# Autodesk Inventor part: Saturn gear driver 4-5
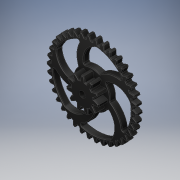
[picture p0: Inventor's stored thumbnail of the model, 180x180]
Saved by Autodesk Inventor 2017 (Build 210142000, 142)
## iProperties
Created: 2016-06
Part Number: Saturn gear driver 4-5
Material: Generic
Document SubType Name: Modeling
Designer: Stan
Density: 1 g/cm^3
Appearance: Glossy - Black
Author: Stan
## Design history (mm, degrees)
sketch "Sketch1"
  geometry: A1 r 17.842 centre (23.318, -32.57) between (7.78, -41.34) and (10.377, -44.853); A2 r 17.842 centre (23.318, -32.57) between (7.78, -41.34) and (10.377, -44.853); A3 r 17.842 centre (-11.479, -38.377) between (4.749, -45.792) and (6.065, -41.626); A4 r 17.842 centre (-11.479, -38.377) between (4.749, -45.792) and (6.065, -41.626); A5 r 17.842 centre (28.361, -28.288) between (14.478, -39.495) and (17.618, -42.533); A6 r 17.842 centre (28.361, -28.288) between (14.478, -39.495) and (17.618, -42.533); A7 r 17.842 centre (-5.006, -39.743) between (12.222, -44.386) and (12.833, -40.06); A8 r 17.842 centre (-5.006, -39.743) between (12.222, -44.386) and (12.833, -40.06); A9 r 17.842 centre (32.631, -23.234) between (20.781, -36.574) and (24.378, -39.053); A10 r 17.842 centre (32.631, -23.234) between (20.781, -36.574) and (24.378, -39.053); A11 r 17.842 centre (1.603, -40.025) between (19.361, -41.769) and (19.252, -37.401); A12 r 17.842 centre (1.603, -40.025) between (19.361, -41.769) and (19.252, -37.401); A13 r 17.842 centre (36.01, -17.546) between (26.518, -32.654) and (30.474, -34.508); A14 r 17.842 centre (36.01, -17.546) between (26.518, -32.654) and (30.474, -34.508); A15 r 17.842 centre (8.17, -39.215) between (25.971, -38.013) and (25.145, -33.722); A16 r 17.842 centre (8.17, -39.215) between (25.971, -38.013) and (25.145, -33.722); A17 r 17.842 centre (38.407, -11.38) between (31.531, -27.844) and (35.738, -29.022); A18 r 17.842 centre (38.407, -11.38) between (31.531, -27.844) and (35.738, -29.022); A19 r 17.842 centre (14.513, -37.336) between (31.874, -33.219) and (30.353, -29.124); A20 r 17.842 centre (14.513, -37.336) between (31.874, -33.219) and (30.353, -29.124); A21 r 17.842 centre (39.756, -4.903) between (35.684, -22.275) and (40.028, -22.744); A22 r 17.842 centre (39.756, -4.903) between (35.684, -22.275) and (40.028, -22.744); A23 r 17.842 centre (20.46, -34.438) between (36.907, -27.52) and (34.733, -23.73); A24 r 17.842 centre (20.46, -34.438) between (36.907, -27.52) and (34.733, -23.73); A25 r 17.842 centre (40.021, 1.707) between (38.863, -16.098) and (43.225, -15.845); A26 r 17.842 centre (40.021, 1.707) between (38.863, -16.098) and (43.225, -15.845); A27 r 17.842 centre (25.849, -30.6) between (40.933, -21.07) and (38.165, -17.69); A28 r 17.842 centre (25.849, -30.6) between (40.933, -21.07) and (38.165, -17.69); A29 r 17.842 centre (39.194, 8.271) between (40.983, -9.481) and (45.244, -8.514); A30 r 17.842 centre (39.194, 8.271) between (40.983, -9.481) and (45.244, -8.514); A31 r 17.842 centre (30.533, -25.928) between (43.843, -14.045) and (40.556, -11.167); A32 r 17.842 centre (30.533, -25.928) between (43.843, -14.045) and (40.556, -11.167); A33 r 17.842 centre (37.298, 14.609) between (41.984, -2.607) and (46.028, -0.951); A34 r 17.842 centre (37.298, 14.609) between (41.984, -2.607) and (46.028, -0.951); A35 r 17.842 centre (34.385, -20.549) between (45.557, -6.637) and (41.841, -4.339); A36 r 17.842 centre (34.385, -20.549) between (45.557, -6.637) and (41.841, -4.339); A37 r 17.842 centre (34.385, 20.549) between (41.841, 4.339) and (45.557, 6.637); A38 r 17.842 centre (34.385, 20.549) between (41.841, 4.339) and (45.557, 6.637); A39 r 17.842 centre (37.298, -14.609) between (46.028, 0.951) and (41.984, 2.607); A40 r 17.842 centre (37.298, -14.609) between (46.028, 0.951) and (41.984, 2.607); A41 r 17.842 centre (30.533, 25.928) between (40.556, 11.167) and (43.843, 14.045); A42 r 17.842 centre (30.533, 25.928) between (40.556, 11.167) and (43.843, 14.045); A43 r 17.842 centre (39.194, -8.271) between (45.244, 8.514) and (40.983, 9.481); A44 r 17.842 centre (39.194, -8.271) between (45.244, 8.514) and (40.983, 9.481); A45 r 17.842 centre (25.849, 30.6) between (38.165, 17.69) and (40.933, 21.07); A46 r 17.842 centre (25.849, 30.6) between (38.165, 17.69) and (40.933, 21.07); A47 r 17.842 centre (40.021, -1.707) between (43.225, 15.845) and (38.863, 16.098); A48 r 17.842 centre (40.021, -1.707) between (43.225, 15.845) and (38.863, 16.098); A49 r 17.842 centre (20.46, 34.438) between (34.733, 23.73) and (36.907, 27.52); A50 r 17.842 centre (20.46, 34.438) between (34.733, 23.73) and (36.907, 27.52); A51 r 17.842 centre (39.756, 4.903) between (40.028, 22.744) and (35.684, 22.275); A52 r 17.842 centre (39.756, 4.903) between (40.028, 22.744) and (35.684, 22.275); A53 r 17.842 centre (14.513, 37.336) between (30.353, 29.124) and (31.874, 33.219); A54 r 17.842 centre (14.513, 37.336) between (30.353, 29.124) and (31.874, 33.219); A55 r 17.842 centre (38.407, 11.38) between (35.738, 29.022) and (31.531, 27.844); A56 r 17.842 centre (38.407, 11.38) between (35.738, 29.022) and (31.531, 27.844); A57 r 17.842 centre (8.17, 39.215) between (25.145, 33.722) and (25.971, 38.013); A58 r 17.842 centre (8.17, 39.215) between (25.145, 33.722) and (25.971, 38.013); A59 r 17.842 centre (36.01, 17.546) between (30.474, 34.508) and (26.518, 32.654); A60 r 17.842 centre (36.01, 17.546) between (30.474, 34.508) and (26.518, 32.654); A61 r 17.842 centre (1.603, 40.025) between (19.252, 37.401) and (19.361, 41.769); A62 r 17.842 centre (1.603, 40.025) between (19.252, 37.401) and (19.361, 41.769); A63 r 17.842 centre (32.631, 23.234) between (24.378, 39.053) and (20.781, 36.574); A64 r 17.842 centre (32.631, 23.234) between (24.378, 39.053) and (20.781, 36.574)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; 1 further point
  constraints: 648 point on circle, 324 centre point, 8 horizontal alignment, 8 vertical alignment, 926 other
extrude "Extrusion1" new body sketch "Sketch1" distance "d0" = 6.35; taper "d1" = 0 deg
fillet "Fillet1" dims "d2" = 1.5875
sketch "Sketch2"
  geometry: A1 r 12.368 centre (-14.047, -4.431) between (-9.384, 7.025) and (-14.519, 7.928); A2 r 12.368 centre (-14.047, -4.431) between (-9.384, 7.025) and (-14.519, 7.928); A3 r 12.368 centre (2.387, 14.534) between (-9.914, 13.243) and (-8.289, 8.289); A4 r 12.368 centre (2.387, 14.534) between (-9.914, 13.243) and (-8.289, 8.289); A5 r 12.368 centre (-9.421, -11.322) between (-11.692, 0.836) and (-16.501, -1.18); A6 r 12.368 centre (-9.421, -11.322) between (-11.692, 0.836) and (-16.501, -1.18); A7 r 12.368 centre (-5.85, 13.517) between (-15.5, 5.781) and (-11.454, 2.492); A8 r 12.368 centre (-5.85, 13.517) between (-15.5, 5.781) and (-11.454, 2.492); A9 r 12.368 centre (-1.805, -14.618) between (-10.288, -5.618) and (-13.243, -9.914); A10 r 12.368 centre (-1.805, -14.618) between (-10.288, -5.618) and (-13.243, -9.914); A11 r 12.368 centre (-12.229, 8.209) between (-16.165, -3.516) and (-10.983, -4.096); A12 r 12.368 centre (-12.229, 8.209) between (-16.165, -3.516) and (-10.983, -4.096); A13 r 12.368 centre (6.385, -13.273) between (-5.618, -10.288) and (-5.781, -15.5); A14 r 12.368 centre (6.385, -13.273) between (-5.618, -10.288) and (-5.781, -15.5); A15 r 12.368 centre (-14.726, 0.294) between (-11.698, -11.698) and (-7.025, -9.384); A16 r 12.368 centre (-14.726, 0.294) between (-11.698, -11.698) and (-7.025, -9.384); A17 r 12.368 centre (12.547, -7.714) between (0.836, -11.692) and (3.516, -16.165); A18 r 12.368 centre (12.547, -7.714) between (0.836, -11.692) and (3.516, -16.165); A19 r 12.368 centre (-12.547, -7.714) between (-3.516, -16.165) and (-0.836, -11.692); A20 r 12.368 centre (-12.547, -7.714) between (-3.516, -16.165) and (-0.836, -11.692); A21 r 12.368 centre (14.726, 0.294) between (7.025, -9.384) and (11.698, -11.698); A22 r 12.368 centre (14.726, 0.294) between (7.025, -9.384) and (11.698, -11.698); A23 r 12.368 centre (-6.385, -13.273) between (5.781, -15.5) and (5.618, -10.288); A24 r 12.368 centre (-6.385, -13.273) between (5.781, -15.5) and (5.618, -10.288); A25 r 12.368 centre (12.229, 8.209) between (10.983, -4.096) and (16.165, -3.516); A26 r 12.368 centre (12.229, 8.209) between (10.983, -4.096) and (16.165, -3.516); A27 r 12.368 centre (1.805, -14.618) between (13.243, -9.914) and (10.288, -5.618); A28 r 12.368 centre (1.805, -14.618) between (13.243, -9.914) and (10.288, -5.618); A29 r 12.368 centre (5.85, 13.517) between (11.454, 2.492) and (15.5, 5.781); A30 r 12.368 centre (5.85, 13.517) between (11.454, 2.492) and (15.5, 5.781); A31 r 12.368 centre (9.421, -11.322) between (16.501, -1.18) and (11.692, 0.836); A32 r 12.368 centre (9.421, -11.322) between (16.501, -1.18) and (11.692, 0.836); A33 r 12.368 centre (-2.387, 14.534) between (8.289, 8.289) and (9.914, 13.243); A34 r 12.368 centre (-2.387, 14.534) between (8.289, 8.289) and (9.914, 13.243); A35 r 12.368 centre (14.047, -4.431) between (14.519, 7.928) and (9.384, 7.025); A36 r 12.368 centre (14.047, -4.431) between (14.519, 7.928) and (9.384, 7.025); A37 r 12.368 centre (-9.866, 10.937) between (2.492, 11.454) and (1.18, 16.501); A38 r 12.368 centre (-9.866, 10.937) between (2.492, 11.454) and (1.18, 16.501); A39 r 12.368 centre (14.212, 3.867) between (7.928, 14.519) and (4.096, 10.983); A40 r 12.368 centre (14.212, 3.867) between (7.928, 14.519) and (4.096, 10.983); A41 r 12.368 centre (2.387, 14.534) between (-9.914, 13.243) and (-8.289, 8.289); A42 r 12.368 centre (-14.047, -4.431) between (-9.384, 7.025) and (-14.519, 7.928); A43 r 12.368 centre (-5.85, 13.517) between (-15.5, 5.781) and (-11.454, 2.492); A44 r 12.368 centre (-9.421, -11.322) between (-11.692, 0.836) and (-16.501, -1.18); A45 r 12.368 centre (-12.229, 8.209) between (-16.165, -3.516) and (-10.983, -4.096); A46 r 12.368 centre (-1.805, -14.618) between (-10.288, -5.618) and (-13.243, -9.914); A47 r 12.368 centre (-14.726, 0.294) between (-11.698, -11.698) and (-7.025, -9.384); A48 r 12.368 centre (6.385, -13.273) between (-5.618, -10.288) and (-5.781, -15.5); A49 r 12.368 centre (-12.547, -7.714) between (-3.516, -16.165) and (-0.836, -11.692); A50 r 12.368 centre (12.547, -7.714) between (0.836, -11.692) and (3.516, -16.165); A51 r 12.368 centre (-6.385, -13.273) between (5.781, -15.5) and (5.618, -10.288); A52 r 12.368 centre (14.726, 0.294) between (7.025, -9.384) and (11.698, -11.698); A53 r 12.368 centre (1.805, -14.618) between (13.243, -9.914) and (10.288, -5.618); A54 r 12.368 centre (12.229, 8.209) between (10.983, -4.096) and (16.165, -3.516); A55 r 12.368 centre (9.421, -11.322) between (16.501, -1.18) and (11.692, 0.836); A56 r 12.368 centre (5.85, 13.517) between (11.454, 2.492) and (15.5, 5.781); A57 r 12.368 centre (14.047, -4.431) between (14.519, 7.928) and (9.384, 7.025); A58 r 12.368 centre (-2.387, 14.534) between (8.289, 8.289) and (9.914, 13.243); A59 r 12.368 centre (14.212, 3.867) between (7.928, 14.519) and (4.096, 10.983); A60 r 12.368 centre (-9.866, 10.937) between (2.492, 11.454) and (1.18, 16.501); A61 r 12.368 centre (9.866, 10.937) between (-1.18, 16.501) and (-2.492, 11.454); A62 r 12.368 centre (-14.212, 3.867) between (-4.096, 10.983) and (-7.928, 14.519); A63 r 12.368 centre (-14.212, 3.867) between (-4.096, 10.983) and (-7.928, 14.519); A64 r 12.368 centre (-14.212, 3.867) between (-4.096, 10.983) and (-7.928, 14.519)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; 1 further point
  constraints: 176 point on circle, 88 centre point, 8 horizontal alignment, 256 other
extrude "Extrusion2" join sketch "Sketch2" distance "d3" = 9.525; taper "d4" = 0 deg
fillet "Fillet2" dims "d5" = 0.79375
fillet "Fillet3" dims "d6" = 0.79375
fillet "Fillet4" dims "d7" = 0.79375
fillet "Fillet5" dims "d8" = 0.79375
fillet "Fillet6" dims "d9" = 0.79375
fillet "Fillet7" dims "d10" = 0.79375
fillet "Fillet8" dims "d11" = 0.79375
body "Solid1"
